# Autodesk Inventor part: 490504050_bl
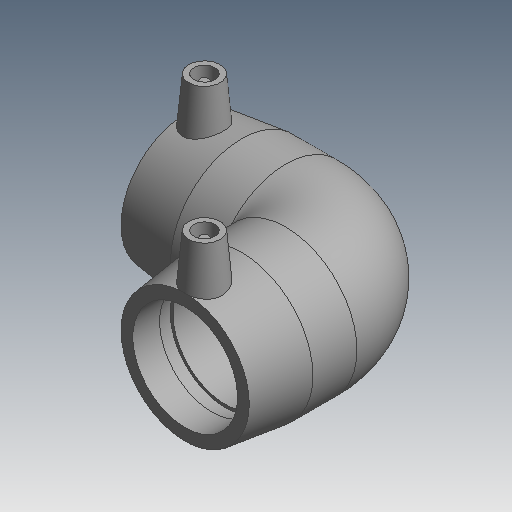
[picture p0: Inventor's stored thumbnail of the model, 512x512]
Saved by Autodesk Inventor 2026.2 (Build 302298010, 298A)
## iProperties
Created: 2017-06
Part Number: 490504050_bl
Material: Generic
Description: PLASSON 90° ELBOW 50
Document SubType Name: Modeling
Designer: KIM
Mass: 55.0731 g
Surface Area: 148.067 cm^2
Volume: 55.0731 cm^3
Density: 1 g/cm^3
Appearance: Default
Author: KIM
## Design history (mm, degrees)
derived "490504 -20-75.ipt"
feature "Solid1::490504 -20-75.ipt" dims "ScaleForDerivedMember" = 10
tag "TaggingFeature1"
body "Solid1"
other parameters: "d2" = 68 [user parameter], "d4" = 27 [user parameter], "d5" = 61.2 [user parameter], "d8" = 168 deg [user parameter], "d10" = 19.2 [user parameter], "d11" = 6.4 [user parameter], "d14" = 17.6296 [user parameter], "d19" = 3.52592 [user parameter], "d20" = 168 deg [user parameter], "d22" = 62.56 [user parameter], "d23" = 68 [user parameter], "d24" = 60.6832 [user parameter], "d29" = 52 [user parameter], "d30" = 15 [user parameter], "d31" = 64.8 [user parameter], "d34" = 5 deg [user parameter], "d35" = 15 [user parameter], "d39" = 5 deg [user parameter], "d41" = 4 [user parameter], "d42" = 14 [user parameter], "d43" = 0 [user parameter], "d45" = 4 [user parameter], "d46" = 14 [user parameter], "d47" = 0 [user parameter], "d50" = 42.5 [user parameter], "d51" = 19.2 [user parameter], "d52" = 48 [user parameter], "d54" = 90 deg [user parameter], "d67" = 45 deg [user parameter], "d71" = 90 deg [user parameter], "d75" = 3.4 [user parameter], "d82" = 45 deg [user parameter], "d83" = 48 [user parameter], "d84" = 61.2 [user parameter], "d87" = 90 deg [user parameter], "d90" = 48 [user parameter], "d91" = 0 [user parameter], "d92" = 48 [user parameter], "d93" = 0 [user parameter], "d94" = 90 deg [user parameter], "d101" = 3 [user parameter], "d102" = 0 [user parameter], "d103" = 3 [user parameter], "d104" = 0 [user parameter], "d105" = 13.92 [user parameter], "d106" = 3.48 [user parameter], "d110" = 26.4 [user parameter], "d111" = 108 [user parameter], "d112" = 108 [user parameter], "d113" = 108 [user parameter], "d114" = 108 [user parameter], "L_" = 108 [user parameter], "L_1" = 48 [user parameter], "D_" = 68 [user parameter], "A_" = 52 [user parameter], "d_2" = 12 [user parameter]
